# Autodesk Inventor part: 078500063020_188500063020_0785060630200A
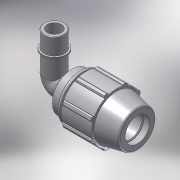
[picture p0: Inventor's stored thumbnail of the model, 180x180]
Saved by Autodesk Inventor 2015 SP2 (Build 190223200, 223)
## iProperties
Created: 2017-02
Part Number: 078500063020_188500063020_0785060630200A
Material: PVC-Piping
Description: PLASSON 90° ELBOW MALE ADAPTOR 63-2"
Document SubType Name: Modeling
Designer: KIM
Mass: 92.6774 g
Surface Area: 199.44 cm^2
Volume: 66.1981 cm^3
Density: 1.4 g/cm^3
Appearance: Smooth - White
Author: KIM
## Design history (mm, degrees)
derived "07850.ipt"
feature "Solid1::07850.ipt"
tag "TaggingFeature1"
body "Solid1"
other parameters: "d2" = 63, "d4" = 14.16667, "d5" = 42.5, "d7" = 113, "d9" = 24.28571, "d11" = 5.66667, "d13" = 120 deg, "d14" = 81.9, "d15" = 12 deg, "d16" = 98.31, "d18" = 3.15, "d19" = 35 deg, "d20" = 17.5 deg, "d21" = 105.09, "d23" = 0, "d25" = 360 deg, "d27" = 2.26, "d33" = 1.26, "d42" = 62.9, "d43" = 3.39, "d46" = 1.89, "d68" = 5.66667, "d72" = 92, "d73" = 59.614, "d74" = 26, "d75" = 68.5561, "d76" = 41.7298, "d77" = 28.6, "d79" = 23.8456, "d80" = 1.78842, "d83" = 0, "d84" = 0, "d91" = 84.75, "d94" = 59.614, "d95" = 41.7298, "d96" = 17, "d97" = 50 deg, "d_" = 63, "E_" = 113, "l_2" = 26, "A_1" = 92, "R_" = 59.614
